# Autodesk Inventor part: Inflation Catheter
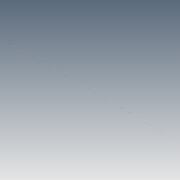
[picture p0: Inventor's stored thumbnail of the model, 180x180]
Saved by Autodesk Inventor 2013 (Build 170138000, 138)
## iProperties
Created: 2013-11
Part Number: Inflation Catheter
Material: Generic
Document SubType Name: Modeling
Designer: Warren
Density: 1 g/cm^3
Author: Warren
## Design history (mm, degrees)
sketch "Sketch1"
  geometry: C1 r 0.05 at (0, 0); 1 further point
  constraints: 1 centre point, 1 coincident
  dimensions: "d0" = 0.1 diameter of C1
extrude "Extrusion3" new body sketch "Sketch1" distance "d7" = 469; taper "d8" = 0 deg
sketch "Sketch2"
  geometry: C1 r 0.05 at (0, 0) reference; C2 r 0.025 at (0, 0)
  constraints: 1 centre point, 1 coincident
  dimensions: "d9" = 0.05 diameter of C2
extrude "Extrusion4" cut sketch "Sketch2" stored distance "d11" = 469; taper "d12" = 0 deg
body "Solid3"
